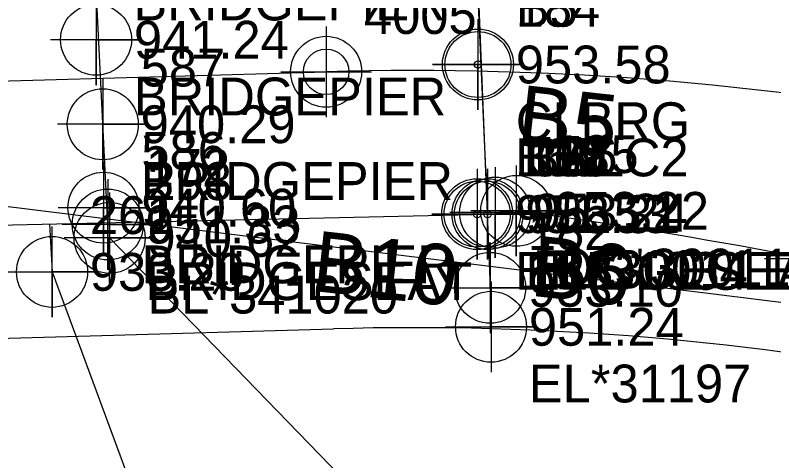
# Model space of a CAD drawing. Extents: x 1150279 to 1151282, y 654632 to 657999.
# Drawn here: x 1150767.1 to 1150817.2, y 657109.7 to 657139.1 of the extents above; entities that cross this region are included whole.
import ezdxf

# ---------------------------------------------------------------- set-up
doc = ezdxf.new("R2010")
doc.units = 0
for name, color, linetype in [('COGO Default Chain', 7, 'Continuous'), ('COGO Default Curve', 7, 'Continuous'), ('Cogo Default Point CELL', 7, 'Continuous'), ('COGO Default Point Elevation', 7, 'Continuous'), ('COGO Default Point Number', 7, 'Continuous'), ('Default Symbol CELL', 7, 'Continuous'), ('Default Symbol Cogo Comment', 7, 'Continuous'), ('Default Symbol Cogo Elevation', 7, 'Continuous'), ('Default Symbol Cogo Number', 7, 'Continuous'), ('Exist Horizontal Alignment', 7, 'Continuous'), ('Exist Horizontal Alignment Station Label', 7, 'Continuous'), ('Exist Hydro Jurisdictional Stream or Body of Water', 7, 'Continuous'), ('Exist Hydro Stream or Body of Water Cogo Elevation', 7, 'Continuous'), ('Exist Hydro Stream or Body of Water Cogo Number', 7, 'Continuous'), ('Exist Hydro Stream or Body of Water Cogo Point CELL', 7, 'Continuous'), ('Exist Other Culture Fence Line', 7, 'Continuous'), ('Exist Other Culture Fence Line Cogo Comment', 7, 'Continuous'), ('Exist Other Culture Fence Line Cogo Elevation', 7, 'Continuous'), ('Exist Other Culture Fence Line Cogo Number', 7, 'Continuous'), ('Exist Other Culture Fence Line Cogo Point CELL', 7, 'Continuous'), ('Exist Other Culture Located Object CELL', 7, 'Continuous'), ('Exist Other Culture Located Object Text', 7, 'Continuous'), ('Exist Right of Way Line', 7, 'Continuous'), ('Exist Roads EOP', 7, 'Continuous'), ('Exist Roads EOP Cogo Comment', 7, 'Continuous'), ('Exist Roads EOP Cogo Elevation', 7, 'Continuous'), ('Exist Roads EOP Cogo Number', 7, 'Continuous'), ('Exist Roads EOP Cogo Point CELL', 7, 'Continuous'), ('Exist Structure Major Bridge Seam', 7, 'Continuous'), ('Exist Structure Major Bridge Seam Cogo Comment', 7, 'Continuous'), ('Exist Structure Major Bridge Seam Cogo Elevation', 7, 'Continuous'), ('Exist Structure Major Bridge Seam Cogo Number', 7, 'Continuous'), ('Exist Structure Major Bridge Seam Cogo Point CELL', 7, 'Continuous'), ('Exist Structure Major Bridge WW', 7, 'Continuous'), ('Exist Structure Major Bridge WW Cogo Comment', 7, 'Continuous'), ('Exist Structure Major Bridge WW Cogo Elevation', 7, 'Continuous'), ('Exist Structure Major Bridge WW Cogo Number', 7, 'Continuous'), ('Exist Structure Major Bridge WW Cogo Point CELL', 7, 'Continuous'), ('Exist Structure Major Deck Tunnel Box Culvert', 7, 'Continuous'), ('Exist Structure Major Deck Tunnel Box Culvert Cogo Elevation', 7, 'Continuous'), ('Exist Structure Major Deck Tunnel Box Culvert Cogo Number', 7, 'Continuous'), ('Exist Structure Major Deck Tunnel Box Culvert Cogo Point CELL', 7, 'Continuous')]:
    doc.layers.add(name, color=color, linetype=linetype)

msp = doc.modelspace()

# ---------------------------------------------------------------- linework, layer by layer
at = {"layer": 'COGO Default Chain'}
for p, q in [((1150614.756, 657145.261), (1150931.292, 657106.062)), ((1150755.797, 657134.446), (1150787.618, 657135.37))]:
    msp.add_line(p, q, dxfattribs=at)
msp.add_arc((1150793.42, 656935.454), 200, 65.68044, 91.66254, dxfattribs=at)
at = {"layer": 'COGO Default Curve'}
msp.add_arc((1150793.42, 656935.454), 200, 65.68044, 91.66254, dxfattribs=at)
at = {"layer": 'Cogo Default Point CELL'}
for points in [[(1150797.64, 657138.851), (1150797.64, 657135.851)], [(1150787.618, 657138.37), (1150787.618, 657135.37)], [(1150787.618, 657138.37), (1150787.618, 657135.37)], [(1150794.64, 657135.851), (1150797.64, 657135.851)], [(1150797.64, 657135.851), (1150800.64, 657135.851)], [(1150797.64, 657135.851), (1150797.64, 657132.851)], [(1150784.618, 657135.37), (1150787.618, 657135.37)], [(1150784.618, 657135.37), (1150787.618, 657135.37)], [(1150787.618, 657135.37), (1150790.618, 657135.37)], [(1150787.618, 657135.37), (1150787.618, 657132.37)], [(1150787.618, 657135.37), (1150790.618, 657135.37)], [(1150787.618, 657135.37), (1150787.618, 657132.37)], [(1150797.59, 657128.96), (1150797.59, 657125.96)], [(1150798.272, 657128.958), (1150798.272, 657125.958)], [(1150794.59, 657125.96), (1150797.59, 657125.96)], [(1150795.272, 657125.958), (1150798.272, 657125.958)], [(1150797.59, 657125.96), (1150800.59, 657125.96)], [(1150797.59, 657125.96), (1150797.59, 657122.96)], [(1150798.272, 657125.958), (1150801.272, 657125.958)], [(1150798.272, 657125.958), (1150798.272, 657122.958)]]:
    msp.add_lwpolyline(points, dxfattribs=at)
for centre in [(1150797.64, 657135.851), (1150787.618, 657135.37), (1150787.618, 657135.37), (1150797.59, 657125.96), (1150798.272, 657125.958)]:
    msp.add_circle(centre, 2.344, dxfattribs=at)
at = {"layer": 'Default Symbol CELL'}
for points in [[(1150772.428, 657140.487), (1150772.428, 657134.487), (1150772.428, 657137.487), (1150775.428, 657137.487), (1150769.428, 657137.487)], [(1150797.64, 657138.851), (1150797.64, 657132.851), (1150797.64, 657135.851), (1150800.64, 657135.851), (1150794.64, 657135.851)], [(1150772.874, 657134.9), (1150772.874, 657128.9), (1150772.874, 657131.9), (1150775.874, 657131.9), (1150769.874, 657131.9)], [(1150772.919, 657129.387), (1150772.919, 657123.387), (1150772.919, 657126.387), (1150775.919, 657126.387), (1150769.919, 657126.387)], [(1150797.59, 657128.96), (1150797.59, 657122.96), (1150797.59, 657125.96), (1150800.59, 657125.96), (1150794.59, 657125.96)], [(1150773.201, 657128.274), (1150773.201, 657122.274), (1150773.201, 657125.274), (1150776.201, 657125.274), (1150770.201, 657125.274)]]:
    msp.add_lwpolyline(points, dxfattribs=at)
for centre in [(1150772.428, 657137.487), (1150797.64, 657135.851), (1150772.874, 657131.9), (1150772.919, 657126.387), (1150797.59, 657125.96), (1150773.201, 657125.274)]:
    msp.add_circle(centre, 2.344, dxfattribs=at)
at = {"layer": 'Exist Horizontal Alignment'}
msp.add_line((1150755.797, 657134.446), (1150787.618, 657135.37), dxfattribs=at)
msp.add_arc((1150793.42, 656935.454), 200, 65.68044, 91.66254, dxfattribs=at)
at = {"layer": 'Exist Horizontal Alignment Station Label'}
msp.add_circle((1150787.618, 657135.37), 1.5, dxfattribs=at)
at = {"layer": 'Exist Hydro Jurisdictional Stream or Body of Water'}
msp.add_lwpolyline([(1150769.348, 657125.308), (1150769.521, 657122.143), (1150780.786, 657091.685), (1150798.339, 657059.295), (1150820.355, 657029.39), (1150829.476, 657003.097)], dxfattribs=at)
at = {"layer": 'Exist Hydro Stream or Body of Water Cogo Point CELL'}
msp.add_lwpolyline([(1150766.521, 657122.143), (1150772.521, 657122.143), (1150769.521, 657122.143), (1150769.521, 657119.143), (1150769.521, 657125.143)], dxfattribs=at)
msp.add_circle((1150769.521, 657122.143), 2.344, dxfattribs=at)
at = {"layer": 'Exist Other Culture Fence Line'}
msp.add_lwpolyline([(1150773.321, 657124.389), (1150794.109, 657102.9), (1150812.457, 657091.594)], dxfattribs=at)
at = {"layer": 'Exist Other Culture Fence Line Cogo Point CELL'}
msp.add_lwpolyline([(1150773.321, 657127.389), (1150773.321, 657121.389), (1150773.321, 657124.389), (1150776.321, 657124.389), (1150770.321, 657124.389)], dxfattribs=at)
msp.add_circle((1150773.321, 657124.389), 2.344, dxfattribs=at)
at = {"layer": 'Exist Other Culture Located Object CELL'}
for centre, radius in [((1150797.64, 657135.851), 2.18), ((1150797.64, 657135.851), 0.24), ((1150798.272, 657125.958), 2.18), ((1150798.272, 657125.958), 0.24)]:
    msp.add_circle(centre, radius, dxfattribs=at)
at = {"layer": 'Exist Other Culture Located Object Text'}
for radius in [2.18, 0.24]:
    msp.add_circle((1150797.59, 657125.96), radius, dxfattribs=at)
at = {"layer": 'Exist Right of Way Line'}
msp.add_line((1150756.29, 657117.453), (1150788.111, 657118.377), dxfattribs=at)
for radius, end in [(213, 88.72471), (183, 91.66254)]:
    msp.add_arc((1150793.42, 656935.454), radius, 65.68044, end, dxfattribs=at)
at = {"layer": 'Exist Roads EOP'}
msp.add_line((1150800.171, 657126.176), (1150798.776, 657126.062), dxfattribs=at)
for centre, major_axis, ratio, start_param, end_param in [((1150800.442, 656964.8), (-177.198, 34.758), 0.999524, 4.48455, 4.91412), ((1150752.571, 656773.823), (-278.809, 220.877), 0.99945, 5.05593, 5.247845)]:
    msp.add_ellipse(centre, major_axis=major_axis, ratio=ratio, start_param=start_param, end_param=end_param, dxfattribs=at)
at = {"layer": 'Exist Roads EOP Cogo Point CELL'}
for points in [[(1150800.171, 657129.176), (1150800.171, 657123.176), (1150800.171, 657126.176), (1150803.171, 657126.176), (1150797.171, 657126.176)], [(1150798.776, 657129.062), (1150798.776, 657123.062), (1150798.776, 657126.062), (1150801.776, 657126.062), (1150795.776, 657126.062)], [(1150819.568, 657125.998), (1150819.568, 657119.998), (1150819.568, 657122.998), (1150822.568, 657122.998), (1150816.568, 657122.998)]]:
    msp.add_lwpolyline(points, dxfattribs=at)
for centre in [(1150798.776, 657126.062), (1150800.171, 657126.176)]:
    msp.add_circle(centre, 2.344, dxfattribs=at)
at = {"layer": 'Exist Structure Major Bridge Seam'}
msp.add_line((1150797.419, 657145.249), (1150798.272, 657125.958), dxfattribs=at)
at = {"layer": 'Exist Structure Major Bridge Seam Cogo Point CELL'}
msp.add_lwpolyline([(1150798.272, 657128.958), (1150798.272, 657122.958), (1150798.272, 657125.958), (1150801.272, 657125.958), (1150795.272, 657125.958)], dxfattribs=at)
msp.add_circle((1150798.272, 657125.958), 2.344, dxfattribs=at)
at = {"layer": 'Exist Structure Major Bridge WW'}
msp.add_lwpolyline([(1150797.283, 657150.154), (1150798.443, 657121.09), (1150798.503, 657118.513)], dxfattribs=at)
at = {"layer": 'Exist Structure Major Bridge WW Cogo Point CELL'}
for points in [[(1150795.443, 657121.09), (1150801.443, 657121.09), (1150798.443, 657121.09), (1150798.443, 657124.09), (1150798.443, 657118.09)], [(1150795.503, 657118.513), (1150801.503, 657118.513), (1150798.503, 657118.513), (1150798.503, 657121.513), (1150798.503, 657115.513)]]:
    msp.add_lwpolyline(points, dxfattribs=at)
for centre in [(1150798.443, 657121.09), (1150798.503, 657118.513)]:
    msp.add_circle(centre, 2.344, dxfattribs=at)
at = {"layer": 'Exist Structure Major Deck Tunnel Box Culvert'}
msp.add_line((1150717.448, 657124.141), (1150798.272, 657125.958), dxfattribs=at)
msp.add_lwpolyline([(1150773.201, 657125.274), (1150772.231, 657144.932)], dxfattribs=at)
at = {"layer": 'Exist Structure Major Deck Tunnel Box Culvert Cogo Point CELL'}
msp.add_lwpolyline([(1150795.272, 657125.958), (1150801.272, 657125.958), (1150798.272, 657125.958), (1150798.272, 657128.958), (1150798.272, 657122.958)], dxfattribs=at)
msp.add_circle((1150798.272, 657125.958), 2.344, dxfattribs=at)

# ---------------------------------------------------------------- texts
at = {"layer": 'COGO Default Point Elevation'}
for s, p in [('953.58', (1150800.14, 657134.601)), ('951.53', (1150800.09, 657124.71)), ('953.31', (1150800.772, 657124.708))]:
    msp.add_text(s, height=2.5, dxfattribs=at).set_placement(p)
at = {"layer": 'COGO Default Point Number'}
for s, p in [('B5', (1150800.14, 657138.351)), ('4005', (1150790.118, 657137.87)), ('B10', (1150800.09, 657128.46)), ('B6', (1150800.772, 657128.458))]:
    msp.add_text(s, height=2.5, dxfattribs=at).set_placement(p)
at = {"layer": 'Default Symbol Cogo Comment'}
for s, p in [('BRIDGEPIER', (1150774.89, 657138.767)), ('BRIDGEPIER', (1150774.928, 657132.487)), ('CLBRG', (1150800.14, 657130.851)), ('BRIDGEPIER', (1150775.374, 657126.9)), ('BRIDGEPIER', (1150775.419, 657121.387)), ('BRIDGESEAT', (1150800.09, 657120.96)), ('BRIDGESEAT', (1150775.701, 657120.274))]:
    msp.add_text(s, height=2.5, dxfattribs=at).set_placement(p)
at = {"layer": 'Default Symbol Cogo Elevation'}
for s, p in [('941.24', (1150774.928, 657136.237)), ('953.58', (1150800.14, 657134.601)), ('940.29', (1150775.374, 657130.65)), ('940.60', (1150775.419, 657125.137)), ('951.53', (1150800.09, 657124.71)), ('951.33', (1150775.701, 657124.024))]:
    msp.add_text(s, height=2.5, dxfattribs=at).set_placement(p)
at = {"layer": 'Default Symbol Cogo Number'}
for s, p in [('184', (1150800.14, 657138.351)), ('587', (1150775.374, 657134.4)), ('586', (1150775.419, 657128.887)), ('169', (1150800.09, 657128.46)), ('172', (1150775.701, 657127.774))]:
    msp.add_text(s, height=2.5, dxfattribs=at).set_placement(p)
at = {"layer": 'Exist Hydro Stream or Body of Water Cogo Elevation'}
msp.add_text('933.20', height=2.5, dxfattribs=at).set_placement((1150772.021, 657120.893))
at = {"layer": 'Exist Hydro Stream or Body of Water Cogo Number'}
msp.add_text('261', height=2.5, dxfattribs=at).set_placement((1150772.021, 657124.643))
at = {"layer": 'Exist Other Culture Fence Line Cogo Comment'}
msp.add_text('BL*341020', height=2.5, dxfattribs=at).set_placement((1150775.821, 657119.389))
at = {"layer": 'Exist Other Culture Fence Line Cogo Elevation'}
msp.add_text('940.62', height=2.5, dxfattribs=at).set_placement((1150775.821, 657123.139))
at = {"layer": 'Exist Other Culture Fence Line Cogo Number'}
msp.add_text('298', height=2.5, dxfattribs=at).set_placement((1150775.821, 657126.889))
at = {"layer": 'Exist Other Culture Located Object Text'}
for s, p in [('B5', (1150800.118, 657130.531)), ('B10', (1150786.588, 657120.897)), ('B6', (1150801.028, 657120.579))]:
    msp.add_text(s, height=4, rotation=353.6867, dxfattribs=at).set_placement(p)
at = {"layer": 'Exist Roads EOP Cogo Comment'}
for s, p in [('OC*30011', (1150802.671, 657121.176)), ('EL*30011', (1150801.276, 657121.062))]:
    msp.add_text(s, height=2.5, dxfattribs=at).set_placement(p)
at = {"layer": 'Exist Roads EOP Cogo Elevation'}
for s, p in [('953.24', (1150801.276, 657124.812)), ('953.22', (1150802.671, 657124.926))]:
    msp.add_text(s, height=2.5, dxfattribs=at).set_placement(p)
at = {"layer": 'Exist Roads EOP Cogo Number'}
for s, p in [('125', (1150802.671, 657128.676)), ('126', (1150801.276, 657128.562))]:
    msp.add_text(s, height=2.5, dxfattribs=at).set_placement(p)
at = {"layer": 'Exist Structure Major Bridge Seam Cogo Comment'}
msp.add_text('EL*31034 EL*31015', height=2.5, dxfattribs=at).set_placement((1150800.772, 657120.958))
at = {"layer": 'Exist Structure Major Bridge Seam Cogo Elevation'}
msp.add_text('953.31', height=2.5, dxfattribs=at).set_placement((1150800.772, 657124.708))
at = {"layer": 'Exist Structure Major Bridge Seam Cogo Number'}
msp.add_text('168', height=2.5, dxfattribs=at).set_placement((1150800.772, 657128.458))
at = {"layer": 'Exist Structure Major Bridge WW Cogo Comment'}
msp.add_text('EL*31197', height=2.5, dxfattribs=at).set_placement((1150801.003, 657113.513))
at = {"layer": 'Exist Structure Major Bridge WW Cogo Elevation'}
for s, p in [('953.10', (1150800.943, 657119.84)), ('951.24', (1150801.003, 657117.263))]:
    msp.add_text(s, height=2.5, dxfattribs=at).set_placement(p)
at = {"layer": 'Exist Structure Major Bridge WW Cogo Number'}
for s, p in [('182', (1150800.943, 657123.59)), ('183', (1150801.003, 657121.013))]:
    msp.add_text(s, height=2.5, dxfattribs=at).set_placement(p)
at = {"layer": 'Exist Structure Major Deck Tunnel Box Culvert Cogo Elevation'}
msp.add_text('953.31', height=2.5, dxfattribs=at).set_placement((1150800.772, 657124.708))
at = {"layer": 'Exist Structure Major Deck Tunnel Box Culvert Cogo Number'}
msp.add_text('CALC2', height=2.5, dxfattribs=at).set_placement((1150800.772, 657128.458))

doc.saveas('drawing.dxf')
